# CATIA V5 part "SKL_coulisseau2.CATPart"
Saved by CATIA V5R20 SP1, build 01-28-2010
Part number: SKL_coulisseau2
Bounding box of the stored display mesh (mm): x -60.104 to 60.104, y -60.104 to 60.104, z -30 to 45
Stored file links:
  C:\Users\Nikow\Documents\IAO\Mécanisme IAO avec squelette\nsarlin\SKL_coulisseau2.CATPart
  J:\IAO\Mecanisme_a_bielle_et_deux_coulisseaux.CATProduct
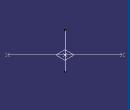
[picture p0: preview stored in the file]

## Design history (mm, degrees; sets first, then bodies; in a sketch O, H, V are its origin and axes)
Set1
  Point1 "Point_coulisseau2": linked copy from another document
  Point2: linked copy from another document
  Point3: linked copy from another document
  Plane1 "Plan_de_ref": linked copy from another document
Body1 (main body)
  Point4: (0, 0, 0), relative to Point1
  Line1 "Gliss": type PtPt, FirstPoint Point2, SecondPoint Point3
  Line2 "Pvt": type Normal, RefPoint Point4, RefSkin Plane1, Start -30, End 45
